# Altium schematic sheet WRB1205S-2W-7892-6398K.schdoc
size 277 x 190 mm; Device: default297x210; Symbol: default297x210; Name: default297x210; Size: "A4"; Id: /; File: WRB1205S-2W-7892-6398K; Sheet: /
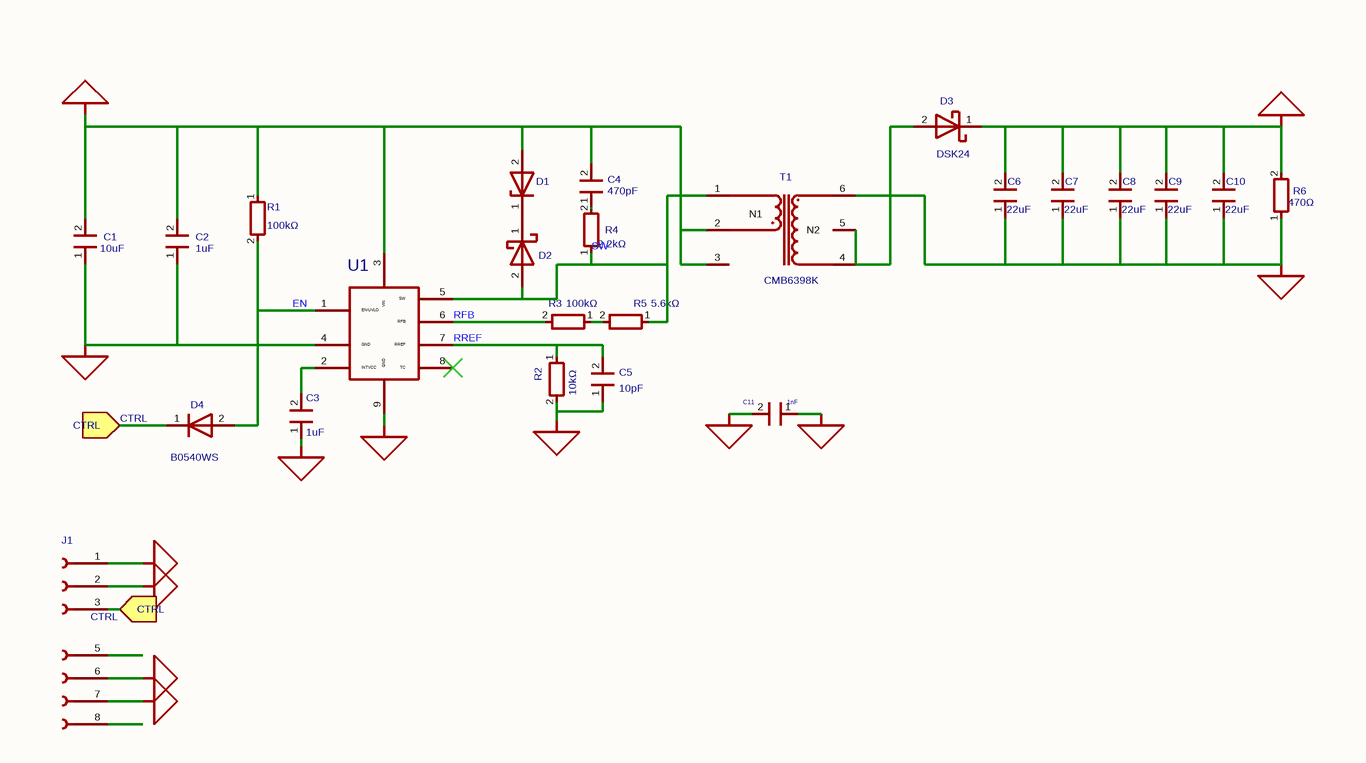
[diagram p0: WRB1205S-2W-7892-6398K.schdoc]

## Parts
C1  10uF  [coileasy:C_0603]
C2  1uF  [coileasy:C_0603]
C3  1uF  [coileasy:C_0603]
C4  470pF  [coileasy:C_0603]
C5  10pF  [coileasy:C_0603]
C6  22uF  [coileasy:C_0603]
C7  22uF  [coileasy:C_0603]
C8  22uF  [coileasy:C_0603]
C9  22uF  [coileasy:C_0603]
C10  22uF  [coileasy:C_0603]
C11  1nF  [coileasy:C_1206]
D1  MM1W24  [Diode_SMD:D_SOD-123]  (value not drawn)
D2  LMBR1100ET1G  [coileasy:SOD-323HE-1]  (value not drawn)
D3  DSK24  [Diode_SMD:D_SOD-123]
D4  B0540WS  [Diode_SMD:D_SOD-323]
J1  Coileasy_Conn_01x07_1  [coileasy:PinHeader_01x07_1_P2.54mm_Vertical]  (value not drawn)
R1  100kΩ  [coileasy:R_0603]
R2  10kΩ  [coileasy:R_0603]
R3  100kΩ  [coileasy:R_0603]
R4  2.2kΩ  [coileasy:R_0603]
R5  5.6kΩ  [coileasy:R_0603]
R6  470Ω  [coileasy:R_0805]
T1  CMB6398K  [MYLibrary:EP5_3+3_7.7x5.3]
U1  CMP7892  [coileasy:ESOP-8]  (value not drawn)

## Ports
CTRL (in)

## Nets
GND1: C1.1 C2.1 C3.1 C5.1 C11.2 J1.1(Pin_1) R2.2 U1.4(GND) U1.9(GND)
GND2: C6.1 C7.1 C8.1 C9.1 C10.1 C11.1 J1.7(Pin_7) R6.1 T1.6
VIN: C1.2 C2.2 C4.2 D1.2(A) J1.2(Pin_2) R1.1 T1.2 T1.3 U1.3(VIN)
VO: C6.2 C7.2 C8.2 C9.2 C10.2 D3.1(K) J1.6(Pin_6) R6.2
CTRL: D4.1(K) J1.3(Pin_3) ; port CTRL
EN: D4.2(A) R1.2 U1.1(EN/UVLO)
RFB: R3.2 U1.6(RFB)
RREF: C5.2 R2.1 U1.7(RREF)
SW: D2.2(A) R4.1 R5.1 T1.1 U1.5(SW)
NetC3_2: C3.2 U1.2(INTVCC)
NetC4_1: C4.1 R4.2
NetD1_1: D1.1(K) D2.1(K)
NetD3_2: D3.2(A) T1.4 T1.5
NetR3_1: R3.1 R5.2

Not connected (* = marked no-connect by the designer): J1 5(Pin_5) 8(Pin_8); U1 8(TC)*

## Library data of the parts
C1 = 0603X106M250NT: 容值:10uF;精度:±20%;额定电压:25V;温度系数:X5R;; Manufacturer: FH(风华); Add into BOM: yes; 3D Model: ac125912035d415993ca9572d50418b1; 3D Model Transform: 62.992,31.496,0,0,0,0,0,0,0; Tolerance: ±20%; Voltage Rating: 25V; Temperature Coefficient: X5R; Symbol: MY_C; ki_keywords: cap capacitor; ki_fp_filters: C_*; UniqueId: 5fb4f22ffcb6a001; ModelName: C0603_L1.6-W0.8-H0.8
C2 = 0603B105K250NT: 容值:1uF;精度:±10%;额定电压:25V;温度系数:X7R;; Manufacturer: FH(风华); Add into BOM: yes; Symbol: MY_C; 3D Model: ac125912035d415993ca9572d50418b1; 3D Model Transform: 62.992,31.496,0,0,0,0,0,0,0; Tolerance: ±10%; Voltage Rating: 25V; Temperature Coefficient: X7R; ki_keywords: cap capacitor; ki_fp_filters: C_*; UniqueId: 21d50210554cb61f; ModelName: C0603_L1.6-W0.8-H0.8
C3 = 0603B105K250NT: 容值:1uF;精度:±10%;额定电压:25V;温度系数:X7R;; Manufacturer: FH(风华); Add into BOM: yes; Symbol: MY_C; 3D Model: ac125912035d415993ca9572d50418b1; 3D Model Transform: 62.992,31.496,0,0,0,0,0,0,0; Tolerance: ±10%; Voltage Rating: 25V; Temperature Coefficient: X7R; ki_keywords: cap capacitor; ki_fp_filters: C_*; UniqueId: ec64484c8c07847f; ModelName: C0603_L1.6-W0.8-H0.8
C4 = CC0603KRX7R9BB471: 容值:470pF;精度:±10%;额定电压:50V;材质(温度系数):X7R;; Manufacturer: YAGEO(国巨); Add into BOM: yes; Symbol: My_library_C; 3D Model: ac125912035d415993ca9572d50418b1; 3D Model Transform: 62.992,31.496,0,0,0,0,0,0,0; Tolerance: ±10%; Voltage Rated: 50V; Temperature Coefficient: X7R; ki_keywords: cap capacitor; ki_fp_filters: C_*; UniqueId: 2b0dbff75b6442fd; ModelName: C0603_L1.6-W0.8-H0.8
C5 = CC0603JRNPO9BN100: 容值:10pF;精度:±5%;额定电压:50V;温度系数:NP0;; Manufacturer: YAGEO(国巨); Add into BOM: yes; 3D Model: ac125912035d415993ca9572d50418b1; 3D Model Transform: 62.992,31.496,0,0,0,0,0,0,0; Tolerance: ±5%; Voltage Rating: 50V; Temperature Coefficient: NP0; Symbol: My_library_C; ki_keywords: cap capacitor; ki_fp_filters: C_*; ModelName: C0603_L1.6-W0.8-H0.8
C6 = 0603X226M100NT: 容值:22uF;精度:±20%;额定电压:10V;温度系数:X5R;; Manufacturer: FH(风华); Add into BOM: yes; 3D Model: ac125912035d415993ca9572d50418b1; 3D Model Transform: 62.992,31.496,0,0,0,0,0,0,0; Tolerance: ±20%; Voltage Rating: 10V; Temperature Coefficient: X5R; Symbol: MY_C; ki_keywords: cap capacitor; ki_fp_filters: C_*; UniqueId: d45ffe04e43665a4; ModelName: C0603_L1.6-W0.8-H0.8
C7 = 0603X226M100NT: 容值:22uF;精度:±20%;额定电压:10V;温度系数:X5R;; Manufacturer: FH(风华); Add into BOM: yes; Symbol: MY_C; 3D Model: ac125912035d415993ca9572d50418b1; 3D Model Transform: 62.992,31.496,0,0,0,0,0,0,0; Tolerance: ±20%; Voltage Rating: 10V; Temperature Coefficient: X5R; ki_keywords: cap capacitor; ki_fp_filters: C_*; UniqueId: 3007ca2539a35480; ModelName: C0603_L1.6-W0.8-H0.8
C8 = 0603X226M100NT: 容值:22uF;精度:±20%;额定电压:10V;温度系数:X5R;; Manufacturer: FH(风华); Add into BOM: yes; Symbol: MY_C; 3D Model: ac125912035d415993ca9572d50418b1; 3D Model Transform: 62.992,31.496,0,0,0,0,0,0,0; Tolerance: ±20%; Voltage Rating: 10V; Temperature Coefficient: X5R; ki_keywords: cap capacitor; ki_fp_filters: C_*; UniqueId: 878ab3ab0cce2757; ModelName: C0603_L1.6-W0.8-H0.8
C9 = 0603X226M100NT: 容值:22uF;精度:±20%;额定电压:10V;温度系数:X5R;; Manufacturer: FH(风华); Add into BOM: yes; 3D Model: ac125912035d415993ca9572d50418b1; 3D Model Transform: 62.992,31.496,0,0,0,0,0,0,0; Tolerance: ±20%; Voltage Rating: 10V; Temperature Coefficient: X5R; Symbol: MY_C; ki_keywords: cap capacitor; ki_fp_filters: C_*; UniqueId: 60e6893b044e2f17; ModelName: C0603_L1.6-W0.8-H0.8
C10 = 0603X226M100NT: 容值:22uF;精度:±20%;额定电压:10V;温度系数:X5R;; Manufacturer: FH(风华); Add into BOM: yes; Symbol: MY_C; 3D Model: ac125912035d415993ca9572d50418b1; 3D Model Transform: 62.992,31.496,0,0,0,0,0,0,0; Tolerance: ±20%; Voltage Rating: 10V; Temperature Coefficient: X5R; ki_keywords: cap capacitor; ki_fp_filters: C_*; UniqueId: c1764753ee6525b4; ModelName: C0603_L1.6-W0.8-H0.8
C11 = CC1206KKX7RDBB102: 容值:1nF;精度:±10%;额定电压:2kV;温度系数:X7R;; Manufacturer: YAGEO(国巨); Add into BOM: yes; Symbol: MY_C; 3D Model: e4be705b945545a48e666415e3682bd8; 3D Model Transform: 125.984,62.992,0,0,0,0,0,0,0; Tolerance: ±10%; Voltage Rating: 2kV; Temperature Coefficient: X7R; ki_keywords: cap capacitor; ki_fp_filters: C_*; UniqueId: b49c3108c5288e9f; ModelName: C1206_L3.2-W1.6-H1.3
D1 = MM1W24_C22395531: 二极管配置:独立式;稳压值(标称值):24V;稳压值(范围):22.8V~26V;耗散功率(Pd):1W;; Manufacturer: R+O(宏嘉诚); Add into BOM: yes; Symbol: Diode_BZV55C75; 3D Model: 0d1aa9d5d9b94beba87ba53253e19c9b; 3D Model Transform: 145.669,70.866,0,180,0,0,0,0,0; Diode Configuration: 独立式; Zener Voltage(Nom): 24V; Reverse Leakage Current (Ir): 5uA; Pd - Power Dissipation: 1W; Impedance(Zzt): 25Ω; Operating Junction Temperature Range: -55℃~+150℃; ki_keywords: zener diode; ki_fp_filters: D*MiniMELF*; Origin Footprint: Diode_SMD:D_MiniMELF; UniqueId: 07a0d5848cd81316; ModelName: SOD-123_L2.8-W1.8-LS3.9-FD
D2 = LMBR1100ET1G_C20622202: 正向压降(Vf):950mV@1.0A;直流反向耐压(Vr):100V;整流电流:1A;; Manufacturer: DOWO(东沃); Add into BOM: yes; 3D Model: 6e7329c6fa044decaae410a44b76a6a6; 3D Model Transform: 98.425,51.181,0,0,0,0,-7.917,0,0; Voltage - DC Reverse(Vr): 100V; Current - Rectified: 1A; Reverse Leakage Current (Ir): 100uA@100V; Non-Repetitive Peak Forward Surge Current: 25A; Symbol: My library_DSS210; Value: DSS210; ki_keywords: diode; ki_fp_filters: TO-???* *_Diode_* *SingleDiode* D_*; ModelName: SOD-323HE_L2.0-W1.4-LS2.5-RD
D3 = DSK24_C64890: 二极管配置:独立式;正向压降(Vf):550mV@2A;直流反向耐压(Vr):40V;整流电流:2A;; Manufacturer: MDD(辰达半导体); Add into BOM: yes; Symbol: My library_DSS210; 3D Model: 7884390a25fb4c08947731ebfba7e3f8; 3D Model Transform: 144.8816,62.992,0,0,0,0,0,0,0; Diode Configuration: 独立式; Voltage - DC Reverse(Vr): 40V; Current - Rectified: 2A; Reverse Leakage Current (Ir): 500uA@40V; Operating Junction Temperature Range: -55℃~+150℃; Value: DSS210; ki_keywords: diode; ki_fp_filters: TO-???* *_Diode_* *SingleDiode* D_*; UniqueId: gge1; ModelName: SOD-123_L2.8-W1.8-LS3.7-RD
D4 = B0540WS_C475613: 二极管配置:独立式;正向压降(Vf):600mV@200mA;直流反向耐压(Vr):40V;整流电流:350mA;; Manufacturer: SHIKUES(时科); Add into BOM: yes; 3D Model: 7459fe65e23146c0a8d836e46a0add72; 3D Model Transform: 104.3305,51.181,0,0,0,0,0,0,0; Diode Configuration: 独立式; Voltage - DC Reverse(Vr): 40V; Current - Rectified: 350mA; Reverse Leakage Current (Ir): 5uA@30V; Non-Repetitive Peak Forward Surge Current: 1.5A; Symbol: Coileasy_D; Value: D; ki_keywords: diode; ki_fp_filters: TO-???* *_Diode_* *SingleDiode* D_*; ModelName: SOD-323_L1.8-W1.3-LS2.5-RD
J1 = Coileasy_Conn_01x07_1: ki_keywords: connector; ki_fp_filters: Connector*:*_1x??_*; Origin Footprint: library:PinHeader_01x07_P2.54mm_Vertical; UniqueId: 9f49826860c2c79d; AddInBom: yes
R1 = RC0603FR-07100KL: 电阻类型:厚膜电阻;阻值:100kΩ;精度:±1%;功率:100mW;最大工作电压:75V;温度系数:±100ppm/℃;; Manufacturer: YAGEO(国巨); Add into BOM: yes; Symbol: Device_R_Small; 3D Model: fc143cca1e79419f9cd78b61e9279f08; 3D Model Transform: 31.8897,63.7794,0,90,0,0,0,0,0; Tolerance: ±1%; Power(Watts): 100mW; Overload Voltage (Max): 75V; ki_keywords: R resistor; ki_fp_filters: R_*; UniqueId: 4e166b190d4de1c3; ModelName: R0603
R2 = RC0603FR-0710KL: 电阻类型:厚膜电阻;阻值:10kΩ;精度:±1%;功率:100mW;最大工作电压:75V;温度系数:±100ppm/℃;; Manufacturer: YAGEO(国巨); Add into BOM: yes; 3D Model: fc143cca1e79419f9cd78b61e9279f08; 3D Model Transform: 31.8897,63.7794,0,90,0,0,0,0,0; Tolerance: ±1%; Power(Watts): 100mW; Overload Voltage (Max): 75V; Symbol: Device_R_Small; ki_keywords: R resistor; ki_fp_filters: R_*; ModelName: R0603
R3 = RC0603FR-07100KL: 电阻类型:厚膜电阻;阻值:100kΩ;精度:±1%;功率:100mW;最大工作电压:75V;温度系数:±100ppm/℃;; Manufacturer: YAGEO(国巨); Add into BOM: yes; 3D Model: fc143cca1e79419f9cd78b61e9279f08; 3D Model Transform: 31.8897,63.7794,0,90,0,0,0,0,0; Tolerance: ±1%; Power(Watts): 100mW; Overload Voltage (Max): 75V; Symbol: Device_R_Small; ki_keywords: R resistor; ki_fp_filters: R_*; ModelName: R0603
R4 = RC0603FR-072K2L: 电阻类型:厚膜电阻;阻值:2.2kΩ;精度:±1%;功率:100mW;工作电压:75V;温度系数:±100ppm/℃;; Manufacturer: YAGEO(国巨); Add into BOM: yes; 3D Model: fc143cca1e79419f9cd78b61e9279f08; 3D Model Transform: 31.8897,63.7794,0,90,0,0,0,0,0; Tolerance: ±1%; Power(Watts): 100mW; Voltage-Supply(Max): 75V; Symbol: Device_R_Small; ki_keywords: R resistor; ki_fp_filters: R_*; ModelName: R0603
R5 = RC0603FR-075K6L: 电阻类型:厚膜电阻;阻值:5.6kΩ;精度:±1%;功率:100mW;工作电压:75V;温度系数:±100ppm/℃;; Manufacturer: YAGEO(国巨); Add into BOM: yes; 3D Model: fc143cca1e79419f9cd78b61e9279f08; 3D Model Transform: 31.8897,63.7794,0,90,0,0,0,0,0; Tolerance: ±1%; Power(Watts): 100mW; Voltage-Supply(Max): 75V; Symbol: Device_R_Small; ki_keywords: R resistor; ki_fp_filters: R_*; ModelName: R0603
R6 = RC0805FR-07470RL: 电阻类型:厚膜电阻;阻值:470Ω;精度:±1%;功率:125mW;工作电压:150V;温度系数:±100ppm/℃;; Manufacturer: YAGEO(国巨); Add into BOM: yes; 3D Model: 37a81e68749a4138bd2dfa6897b24b85; 3D Model Transform: 78.74,51.181,0,0,0,0,0,-0.0005,0; Tolerance: ±1%; Power(Watts): 125mW; Voltage-Supply(Max): 150V; Symbol: Device_R_Small; ki_keywords: R resistor; ki_fp_filters: R_*; UniqueId: c9a24d22ca7022dc; ModelName: R0805_L2.0-W1.3-H0.6
T1 = CMB6398K: Manufacturer: coileasy(线易); Add into BOM: yes; Symbol: CMT_3+3_1
U1 = CMP7892: Manufacturer: coileasy(线易); AddInBom: yes; ModelId: f43fc10339aa42ce991094e4756959b90819f05c4eef4c71ace90d822a990e87; ModelName: ESOP-8_L4.9-W3.9-P1.27-LS6.0-BL-EP3.3; ModelTransform: 192.913,236.22,0,0,0,0,0,0,0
